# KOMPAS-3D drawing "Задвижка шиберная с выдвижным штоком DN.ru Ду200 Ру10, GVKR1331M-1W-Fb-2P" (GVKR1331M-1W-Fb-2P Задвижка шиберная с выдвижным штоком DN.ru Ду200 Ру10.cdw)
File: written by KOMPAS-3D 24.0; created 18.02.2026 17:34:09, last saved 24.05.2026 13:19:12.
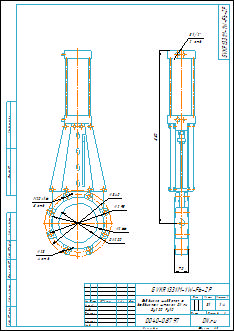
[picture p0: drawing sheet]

Document properties: Автор: R2D2; Форматы листов документа: A3; Полное имя файла: GVKR1331M-1W-Fb-2P Задвижка шиберная с выдвижным штоком DN.ru Ду200 Ру10.m3d; Масса: 31; Наименование: Задвижка шиберная с выдвижным штоком DN.ru Ду200 Ру10; Количество листов документа: 1; Примечание: D040-08797

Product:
- Part/product: Задвижка шиберная с выдвижным штоком DN.ru Ду200 Ру10  | designation GVKR1331M-1W-Fb-2P
    Масса: 31
    Раздел спецификации: Прочие изделия
    Примечание: D040-08797

Views: Вид 1, Спереди, Проекционный вид 2
Referenced files in E:\Работа\Зайцев\GVKR1331N-2W-Fb-S Задвижка шиберная с выдвижным штоком DN.ru Ду50-300 Ру10\DN50\: GVKR1331N-2W-Fb-S Задвижка шиберная DN.ru Ду50 Ру10.m3d
Referenced files in E:\Работа\Зайцев\GVKR1331M-1W-Fb-2P Задвижка шиберная с выдвижным штоком DN.ru Ду50-300 Ру16-10-6 с пневмоприводом\исходные материалы\DN200\DN200\: GVKR1331M-1W-Fb-2P Задвижка шиберная с выдвижным штоком DN.ru Ду200 Ру10.m3d
Referenced files in E:\Работа\Зайцев\Для компаса\: чертеж DN.ru А3.cdt
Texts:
  GVKR1331M-1W-Fb-2P
  чертеж DN.ru А3.cdt
  Задвижка шиберная с
  выдвижным штоком DN.ru
  Ду200 Ру10
  Задвижка шиберная с выдвижным штоком DN.ru Ду200 Ру10
  GVKR1331M-1W-Fb-2P Задвижка шиберная с выдвижным штоком DN.ru Ду200 Ру10
Dimensions and other numbers on the sheet: 0; 3; 2; 4; 20; 8 отв.; 23; 4 отв.; 340; 266; 295; 200; 2 отв.; 70; 880; 1:4; 1; 31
